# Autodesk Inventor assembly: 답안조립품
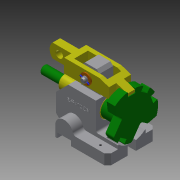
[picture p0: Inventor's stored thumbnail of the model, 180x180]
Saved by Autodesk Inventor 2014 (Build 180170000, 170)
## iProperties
Created: 2016-11
Part Number: 답안조립품
Document SubType Name: Assembly
Designer: net
Author: net
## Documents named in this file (8)
- C:\Users\net\Desktop\461107V1003\답안조립품.iam
- C:\Users\net\Desktop\461107V1003\본체.ipt
- C:\Users\net\Desktop\461107V1003\분할축.ipt
- C:\Users\net\Desktop\461107V1003\부시.ipt
- C:\Users\net\Desktop\461107V1003\분할대.ipt
- C:\Users\net\Desktop\461107V1003\와셔.ipt
- C:\Users\net\Desktop\461107V1003\클레비스핀.ipt
- C:\Users\net\Desktop\461107V1003\원통형핀.ipt
